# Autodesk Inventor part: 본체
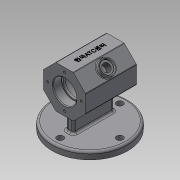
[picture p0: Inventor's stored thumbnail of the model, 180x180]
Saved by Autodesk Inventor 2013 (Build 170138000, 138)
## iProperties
Created: 2021-02
Part Number: 본체
Material: 일반
Document SubType Name: Modeling
Designer: default
Density: 1 g/cm^3
Author: default
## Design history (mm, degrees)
sketch "스케치1"
  geometry: C1 r 52 at (0, 0); 1 further point
  constraints: 1 centre point, 1 coincident
  dimensions: "d0" = 104 diameter of C1
extrude "돌출1" new body sketch "스케치1" distance "d2" = 10; taper "d3" = 0 deg
sketch "스케치2" dims "d4" = 82
  geometry: C1 r 52 at (0, 0) reference; 1 further point
  constraints: 2 vertical alignment, 2 other
hole "구멍1" sketch "스케치2" at (0, 41) diameter "d6" = 9; stored, may be unused: countersink angle "d10" = 90 deg, drill point angle "d12" = 118 deg; dims "d7" = 6, "d8" = 4, "d9" = 2, "d11" = 8
sketch "스케치9"
  geometry: L1 (12.012, 33)-(-12.012, 33); L2 (-12.012, 33)-(-29, 49.988); L3 (-29, 49.988)-(-29, 74.012); L4 (-29, 74.012)-(-12.012, 91); L5 (-12.012, 91)-(12.012, 91); L6 (12.012, 91)-(29, 74.012); L7 (29, 74.012)-(29, 49.988); L8 (29, 49.988)-(12.012, 33); L9 (4.5, 0)-(-4.5, 0) reference; L10 (-52, 0)-(52, 0) reference; 3 further points
  constraints: 16 end point, 2 vertical alignment, 1 midpoint, 17 other
  dimensions: "d53" = 62 distance from line of L9 point (0, 62); "d54" = 91 distance between parallel lines of L10 L5
extrude "돌출4" join sketch "스케치9" stored distance "d55" = 70; taper "d56" = 0 deg
sketch "스케치10"
  geometry: L1 (-35, 74.012)-(-35, 49.988) reference; L2 (35, 49.988)-(35, 74.012) reference; L3 (-35, 62)-(35, 62); L4 (-35, 91)-(-35, 74.012) reference; L5 (35, 74.012)-(35, 91) reference; L6 (-35, 78)-(-23.3, 78); L7 (-23, 77.7)-(-23, 76); L8 (-23, 76)-(-20, 76); L9 (-20, 76)-(-20, 81); L10 (-17, 84)-(17, 84); L11 (20, 81)-(20, 76); L12 (20, 76)-(23, 76); L13 (23, 76)-(23, 77.7); L14 (23.3, 78)-(35, 78); A1 r 0.3 centre (-23.3, 77.7) between (-23, 77.7) and (-23.3, 78); A2 r 0.3 centre (23.3, 77.7) between (23.3, 78) and (23, 77.7); A3 r 3 centre (-17, 81) between (-17, 84) and (-20, 81); A4 r 3 centre (17, 81) between (20, 81) and (17, 84); 4 further points
  constraints: 20 end point, 8 point on circle, 8 point on line, 8 tangent, 6 parallel, 4 centre point, 4 equal length, 3 perpendicular, 2 equal radius, 2 midpoint
  dimensions: "d65" = 32 diameter of L6 L3; "d67" = 28 diameter of L8 L3; "d68" = 44 diameter of L10 L3; "d69" = 12 distance of L6.start point (-23, 78); "d70" = 40 distance of point (-20, 84) point (20, 84); "d71" = 0.3 radius of A1; "d72" = 3 radius of A3
revolve "회전2" sketch "스케치10" stored, may be unused: angle "d73" = 90 deg
chamfer "모따기2" distance "d74" = 1; stored, may be unused: second distance "d75" = 2, angle "d76" = 45 deg
sketch "스케치11" dims "d77" = 46
  geometry: C1 r 17 at (0, 62) reference; 2 further points
  constraints: 2 vertical alignment, 2 other
hole "구멍3" sketch "스케치11" at (0, 85) diameter "d79" = 3.242; stored, may be unused: countersink angle "d83" = 90 deg, drill point angle "d85" = 118 deg; dims "d80" = 8, "d81" = 4, "d82" = 2, "d84" = 10
sketch "스케치12"
  geometry: L1 (-5, -28)-(5, -28); L2 (5, -28)-(5, 28); L3 (5, 28)-(-5, 28); L4 (-5, 28)-(-5, -28); L5 (-5, -28)-(5, 28); L6 (5, -28)-(-5, 28); C1 r 52 at (0, 0) reference
  constraints: 12 end point, 2 midpoint, 2 parallel, 1 horizontal, 1 perpendicular
  dimensions: "d89" = 10 distance of L2.end L3.end; "d91" = 56 distance of L1.end L2.end
extrude "돌출5" join sketch "스케치12" stored distance "d92" = 70; taper "d93" = 0 deg
sketch "스케치13"
  geometry: L1 (-24.024, 70)-(0, 70) reference; L2 (-41.012, 70)-(-41.012, 0) reference; C1 r 10 at (-12.012, 35); 1 further point
  constraints: 1 centre point
  dimensions: "d94" = 29 distance from line of L2 C1.centre; "d95" = 35 distance from line of L1 C1.centre; "d96" = 20 diameter of C1
extrude "돌출6" join sketch "스케치13" distance "d97" = 5; taper "d98" = 0 deg
sketch "스케치14"
  geometry: C1 r 10 at (0, 0) reference; 1 further point
hole "구멍4" sketch "스케치14" at (0, 0) diameter "d99" = 10.917; stored, may be unused: countersink angle "d103" = 90 deg, drill point angle "d105" = 118 deg; dims "d100" = 8, "d101" = 16, "d102" = 2, "d104" = 10
chamfer "모따기3" distance "d106" = 1; stored, may be unused: second distance "d107" = 2, angle "d108" = 45 deg
fillet "모깎기1" dims "d109" = 1
fillet "모깎기2" dims "d110" = 1
fillet "모깎기3" dims "d111" = 3
fillet "모깎기4" dims "d112" = 3
fillet "모깎기5" dims "d113" = 3
sketch "스케치15"
  geometry: L1 (0, 70)-(23.196, 70) reference; L2 (-17.109, 0)-(-17.109, 70) reference; 2 further points
  constraints: 1 other
  dimensions: "d114" = 29 distance from line of L2 point (11.891, 35); "d115" = 35 distance from line of L1 point (11.891, 35)
feature "엠보싱1" sketch "스케치15" dims "d53" = 62, "d54" = 91, "d116" = 0.5, "d117" = 0
node "솔리드1"
pattern_circular "원형 패턴1" dims angle "d14" = 360 deg
pattern_circular "원형 패턴3" dims angle "d87" = 360 deg
mirror "대칭2"
